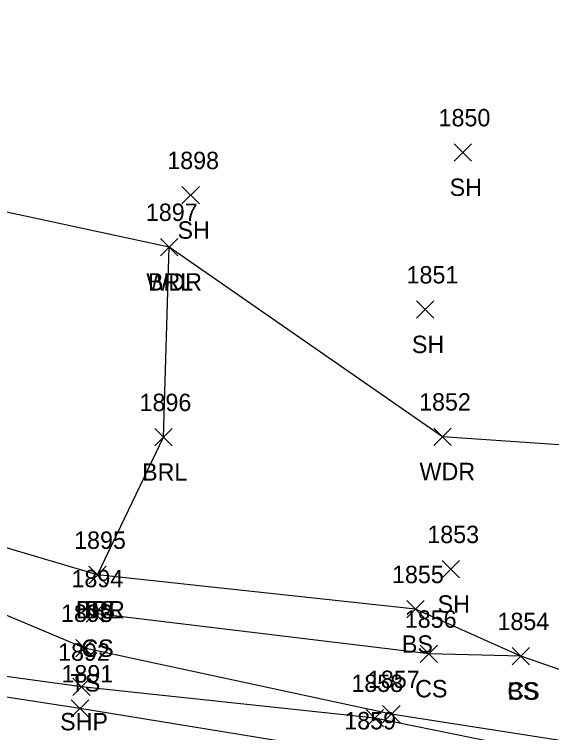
# Model space of a CAD drawing. Extents: x 1497084 to 1499861, y 734741 to 735567.
# Drawn here: x 1499680 to 1499741.8, y 735456.1 to 735538.6 of the extents above; entities that cross this region are included whole.
import ezdxf

# ---------------------------------------------------------------- set-up
doc = ezdxf.new("R2010")
doc.units = 0
for name, color, linetype in [('L_A', 7, 'Continuous'), ('L_I', 7, 'Continuous'), ('L_TIC', 7, 'Continuous'), ('LABL', 7, 'Continuous'), ('LAWA', 7, 'Continuous'), ('LELB', 7, 'Continuous'), ('P_A', 7, 'Continuous'), ('P_I', 7, 'Continuous'), ('P_TIC', 7, 'Continuous'), ('PET', 7, 'Continuous'), ('PSP', 7, 'Continuous')]:
    doc.layers.add(name, color=color, linetype=linetype)

msp = doc.modelspace()

# ---------------------------------------------------------------- linework, layer by layer
at = {"layer": 'L_TIC'}
for points in [[(1499730.541, 735521.759), (1499732.541, 735523.759)], [(1499732.541, 735521.759), (1499730.541, 735523.759)], [(1499699.262, 735516.841), (1499701.262, 735518.841)], [(1499701.262, 735516.841), (1499699.262, 735518.841)], [(1499696.802, 735510.882), (1499698.802, 735512.882)], [(1499698.802, 735510.882), (1499696.802, 735512.882)], [(1499696.802, 735510.882), (1499698.802, 735512.882)], [(1499698.802, 735510.882), (1499696.802, 735512.882)], [(1499726.204, 735503.697), (1499728.204, 735505.697)], [(1499728.204, 735503.697), (1499726.204, 735505.697)], [(1499696.132, 735489.029), (1499698.132, 735491.029)], [(1499698.132, 735489.029), (1499696.132, 735491.029)], [(1499728.211, 735489.085), (1499730.211, 735491.085)], [(1499730.211, 735489.085), (1499728.211, 735491.085)], [(1499729.159, 735473.855), (1499731.159, 735475.855)], [(1499731.159, 735473.855), (1499729.159, 735475.855)], [(1499688.554, 735473.192), (1499690.554, 735475.192)], [(1499690.554, 735473.192), (1499688.554, 735475.192)], [(1499688.554, 735473.192), (1499690.554, 735475.192)], [(1499690.554, 735473.192), (1499688.554, 735475.192)], [(1499688.554, 735473.192), (1499690.554, 735475.192)], [(1499690.554, 735473.192), (1499688.554, 735475.192)], [(1499688.25, 735468.78), (1499690.25, 735470.78)], [(1499690.25, 735468.78), (1499688.25, 735470.78)], [(1499725.099, 735469.252), (1499727.099, 735471.252)], [(1499727.099, 735469.252), (1499725.099, 735471.252)], [(1499687.043, 735464.791), (1499689.043, 735466.791)], [(1499689.043, 735464.791), (1499687.043, 735466.791)], [(1499726.625, 735464.123), (1499728.625, 735466.123)], [(1499728.625, 735464.123), (1499726.625, 735466.123)], [(1499737.222, 735463.854), (1499739.222, 735465.854)], [(1499739.222, 735463.854), (1499737.222, 735465.854)], [(1499737.222, 735463.854), (1499739.222, 735465.854)], [(1499739.222, 735463.854), (1499737.222, 735465.854)], [(1499722.327, 735457.194), (1499724.327, 735459.194)], [(1499724.327, 735457.194), (1499722.327, 735459.194)]]:
    msp.add_lwpolyline(points, dxfattribs=at)
at = {"layer": 'LABL'}
for points in [[(1499689.554, 735474.192), (1499666.752, 735480.946), (1499644.867, 735476.617), (1499599.291, 735481.733), (1499595.722, 735488.498), (1499603.208, 735511.359), (1499612.735, 735535.087)], [(1499689.554, 735474.192), (1499697.132, 735490.029), (1499697.802, 735511.882)]]:
    msp.add_lwpolyline(points, dxfattribs=at)
at = {"layer": 'LAWA'}
msp.add_lwpolyline([(1499788.738, 735496.153), (1499778.307, 735474.671), (1499770.599, 735459.37), (1499768.79, 735460.678), (1499758.938, 735469.149), (1499746.531, 735488.898), (1499729.211, 735490.085), (1499697.802, 735511.882), (1499637.791, 735524.775), (1499612.735, 735535.087), (1499594.485, 735538.631)], dxfattribs=at)
at = {"layer": 'LELB'}
for points in [[(1499783.41, 735497.745), (1499775.463, 735477.276), (1499768.79, 735460.678), (1499765.566, 735458.329), (1499760.416, 735458.461), (1499754.316, 735459.261), (1499738.222, 735464.854), (1499726.099, 735470.252), (1499689.554, 735474.192)], [(1499770.599, 735459.37), (1499767.316, 735451.404), (1499753.266, 735453.514), (1499723.327, 735458.194), (1499688.043, 735465.791), (1499662.005, 735476.729), (1499649.942, 735471.977), (1499600.229, 735477.808), (1499596.973, 735472.366)], [(1499738.222, 735464.854), (1499727.625, 735465.123), (1499689.25, 735469.78)]]:
    msp.add_lwpolyline(points, dxfattribs=at)
at = {"layer": 'P_TIC'}
for points in [[(1499686.714, 735460.331), (1499688.714, 735462.331)], [(1499688.714, 735460.331), (1499686.714, 735462.331)], [(1499686.533, 735457.833), (1499688.533, 735459.833)], [(1499688.533, 735457.833), (1499686.533, 735459.833)], [(1499720.433, 735456.745), (1499722.433, 735458.745)], [(1499722.433, 735456.745), (1499720.433, 735458.745)]]:
    msp.add_lwpolyline(points, dxfattribs=at)
at = {"layer": 'PET'}
msp.add_lwpolyline([(1499846.488, 735425.23), (1499785.866, 735440.032), (1499753.42, 735446.608), (1499720.619, 735453.442), (1499687.533, 735458.833), (1499650.762, 735464.505), (1499635.869, 735466.456), (1499596.077, 735469.991)], dxfattribs=at)
at = {"layer": 'PSP'}
msp.add_lwpolyline([(1499847.595, 735429.73), (1499789.267, 735443.962), (1499769.135, 735448.7), (1499753.081, 735451.309), (1499721.433, 735457.745), (1499687.714, 735461.331), (1499651.835, 735466.256), (1499635.869, 735466.456)], dxfattribs=at)

# ---------------------------------------------------------------- texts
at = {"layer": 'L_A'}
for s, p in [('SH', (1499730.029, 735517.759)), ('SH', (1499698.75, 735512.841)), ('WDR', (1499695.164, 735506.882)), ('BRL', (1499695.345, 735506.882)), ('SH', (1499725.693, 735499.697)), ('BRL', (1499694.675, 735485.029)), ('WDR', (1499726.573, 735485.085)), ('SH', (1499728.647, 735469.855)), ('BRR', (1499687.042, 735469.192)), ('BRL', (1499687.097, 735469.192)), ('BS', (1499687.995, 735469.192)), ('BS', (1499724.54, 735465.252)), ('CS', (1499687.691, 735464.78)), ('TS', (1499686.452, 735460.791)), ('CS', (1499726.066, 735460.123)), ('CS', (1499736.663, 735459.854)), ('BS', (1499736.663, 735459.854))]:
    msp.add_text(s, height=2, dxfattribs=at).set_placement(p)
at = {"layer": 'L_I'}
for s, p in [('1850', (1499728.761, 735525.759)), ('1898', (1499697.569, 735520.841)), ('1897', (1499695.109, 735514.882)), ('1897', (1499695.109, 735514.882)), ('1851', (1499725.078, 735507.697)), ('1896', (1499694.384, 735493.029)), ('1852', (1499726.518, 735493.085)), ('1853', (1499727.466, 735477.855)), ('1895', (1499686.861, 735477.192)), ('1895', (1499686.861, 735477.192)), ('1895', (1499686.861, 735477.192)), ('1894', (1499686.557, 735472.78)), ('1855', (1499723.406, 735473.252)), ('1893', (1499685.35, 735468.791)), ('1856', (1499724.877, 735468.123)), ('1854', (1499735.529, 735467.854)), ('1854', (1499735.529, 735467.854)), ('1857', (1499720.634, 735461.194))]:
    msp.add_text(s, height=2, dxfattribs=at).set_placement(p)
at = {"layer": 'P_A'}
msp.add_text('SHP', height=2, dxfattribs=at).set_placement((1499685.25, 735456.331))
at = {"layer": 'P_I'}
for s, p in [('1892', (1499685.021, 735464.331)), ('1891', (1499685.407, 735461.833)), ('1858', (1499718.74, 735460.745)), ('1859', (1499717.918, 735456.442))]:
    msp.add_text(s, height=2, dxfattribs=at).set_placement(p)

doc.saveas('drawing.dxf')
